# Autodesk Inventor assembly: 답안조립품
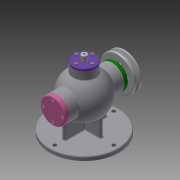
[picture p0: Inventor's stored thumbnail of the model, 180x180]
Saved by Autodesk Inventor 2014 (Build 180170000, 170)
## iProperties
Created: 2020-08
Part Number: 답안조립품
Document SubType Name: Assembly
Designer: kh
Author: kh
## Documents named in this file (18)
- C:\Users\kh\Desktop\700806V1033\답안조립품.iam
- C:\Users\kh\Desktop\700806V1033\본체.ipt
- C:\Users\kh\Desktop\700806V1033\V-벨트풀리.ipt
- C:\Users\kh\Desktop\700806V1033\너트 M8.ipt
- C:\Users\kh\Desktop\700806V1033\뒤커버.ipt
- C:\Users\kh\Desktop\700806V1033\멈춤링 15x1.ipt
- C:\Users\kh\Desktop\700806V1033\멈춤링 35x1.6.ipt
- 멈춤링 35x1.6.ipt
- C:\Users\kh\Desktop\700806V1033\베어링 6202.ipt
- 베어링 6202.ipt
- C:\Users\kh\Desktop\700806V1033\볼트 M4.ipt
- C:\Users\kh\Desktop\700806V1033\상부커버.ipt
- C:\Users\kh\Desktop\700806V1033\슬라이드.ipt
- C:\Users\kh\Desktop\700806V1033\앞커버.ipt
- C:\Users\kh\Desktop\700806V1033\오일 실 15 30 7.ipt
- C:\Users\kh\Desktop\700806V1033\칼라.ipt
- C:\Users\kh\Desktop\700806V1033\키 3x3x12.ipt
- C:\Users\kh\Desktop\700806V1033\편심축.ipt
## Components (1 placed, 1 different names)
1. V-벨트풀리:1 — Insert:15, Mate:6, Insert:16
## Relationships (3: Insert 2, Mate 1)
- Insert:15: V-벨트풀리:1
- Mate:6: V-벨트풀리:1
- Insert:16: V-벨트풀리:1
